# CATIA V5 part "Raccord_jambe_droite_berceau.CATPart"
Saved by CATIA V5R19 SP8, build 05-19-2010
Part number: Raccord_jambe_droite_berceau
Bounding box of the stored display mesh (mm): x 555 to 900, y -1185 to -825, z -35 to 310
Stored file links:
  G:\EU_thinkMotion\CFAO_2010\MMS_groupe2\MMS_groupe2\OK\mmartini\mmartiniCFAO\Raccord_jambe_droite_berceau.CATPart
  C:\Users\Mathieu Martini\Desktop\CFAO\Animation\CFAO.CATProduct
  G:\EU_thinkMotion\CFAO_2010\MMS_groupe2\MMS_groupe2\OK\mmartini\mmartiniCFAO\Squelette.CATPart
  G:\EU_thinkMotion\CFAO_2010\MMS_groupe2\MMS_groupe2\OK\mmartini\mmartiniCFAO\jambe_roue_droite.CATPart
  G:\EU_thinkMotion\CFAO_2010\MMS_groupe2\MMS_groupe2\OK\mmartini\mmartiniCFAO\bielle_droite.CATPart
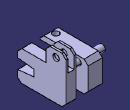
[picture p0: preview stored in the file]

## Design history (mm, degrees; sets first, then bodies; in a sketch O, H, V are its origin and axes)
External parameters (linked from other documents)
  External.diametre_canon = 150 mm
  External.diametre_verin = 120 mm
AxisSystem1: origin (0, 0, 0), X (1, 0, 0), Y (0, 1, 0), Z (0, 0, 1)
Set1
  Sketch1 on Plane1, origin (675, 0, 0), H (0, 1, 0), V (0, 0, 1)
    line L1 (-1185, 190) -> (-825, 190)
    line L2 (-825, 190) -> (-825, -35)
    line L3 (-825, -35) -> (-1185, -35)
    line L4 (-1185, -35) -> (-1185, 190)
    reference projected point E1 (-900, 150) from Line1
    reference projected point E2 (-900, 150) from Line1
    distance E1 L1 = 40 {= External.diametre_verin /3}
    distance L2 E2 = 75 {= External.diametre_canon /2}
    distance L2 L4 = 360 {= External.diametre_verin *3}
    distance L3 L1 = 225 {= External.diametre_canon *1.5}
    horizontal: L1 H, L3 H
    vertical: L2 V, L4 V
Set2
  Plane1 "Plan_verin_droit": linked copy from another document
  Line1 "axe_berceau_jambe": linked copy from another document
  Plane2 "Plan_rayon_ext_verin_droit": linked copy from another document
  Plane3 "Plan_rayon_int_verin_droit": linked copy from another document
  Line2 "Droite_plan_de_construction_verin": linked copy from another document
Body1 (main body)
  Pad1: profile Sketch1, direction (1, 0, 0), up to Plane3, offset -13.6364 {= -External.diametre_canon /11}, opposite side up to Plane2
  Sketch2 on Plane1, origin (675, 0, 0), H (0, 1, 0), V (0, 0, 1)
    circle A1 centre (-900, 150) radius 24
    point P1 (-900, 150)
    reference projected point E1 (-900, 150) from Line1
    radius A1 = 24 {= External.diametre_verin /5}
    coincidence: P1 E1
  Pad2: profile Sketch2, direction (1, 0, 0), length 150 {= External.diametre_canon}, opposite side length 120 {= External.diametre_verin}
  Sketch3 on face of Pad1 from Sketch1.L1, origin (0, 0, 190), H (1, 0, 0), V (0, 1, 0)
    circle A1 centre (675, -1125) radius 24
    point P1 (675, -1125)
    reference projected line E1 through (0, -900) direction (1, 0) from Line1
    reference projected line E2 through (675, 0) direction (0, -1) from Line2
    distance P1 E1 = 225 {= External.diametre_canon *1.5}
    radius A1 = 24 {= External.diametre_verin /5}
    coincidence: P1 E2
  Pocket1: profile Sketch3, direction (0, 0, -1), through (limit type 6)
  Sketch4 on face of Pad1 from Sketch1.L4, origin (0, -1185, 0), H (1, 0, 0), V (0, 0, 1)
    line L1 (628.6364, 152.5) -> (735, 152.5)
    line L2 (735, 152.5) -> (735, 2.5)
    line L3 (735, 2.5) -> (628.6364, 2.5)
    line L4 (628.6364, 2.5) -> (628.6364, 152.5)
    reference projected line E1 (628.6364, -35) -> (628.6364, 190) from edge [face of Pad1 from Sketch1.L4 | end face of Pad1]
    reference projected line E2 (735, 190) -> (735, -35) from edge [face of Pad1 from Sketch1.L4 | start face of Pad1]
    reference projected line E3 (628.6364, -35) -> (735, -35) from edge [face of Pad1 from Sketch1.L3 | face of Pad1 from Sketch1.L4]
    reference projected line E4 (735, 190) -> (628.6364, 190) from edge [face of Pad1 from Sketch1.L1 | face of Pad1 from Sketch1.L4]
    distance L3 E3 = 37.5 {= External.diametre_canon /4}
    distance E4 L1 = 37.5 {= External.diametre_canon /4}
    horizontal: L1 H, L3 H
    vertical: L2 V, L4 V
    coincidence: E1 L4, E2 L2
  Pocket2: profile Sketch4, direction (0, 1, 0), length 125 {= External.diametre_canon /1.2}
  Sketch5 on end face of Pad2, origin (825, 0, 0), H (0, 1, 0), V (0, 0, 1)
    projected line E1 (-1185, 190) -> (-825, 190) from edge [start face of Pad1 | face of Pad1 from Sketch1.L1]
    projected line E2 (-825, -35) -> (-825, 190) from edge [face of Pad1 from Sketch1.L2 | start face of Pad1]
    projected line E3 (-825, -35) -> (-1185, -35) from edge [start face of Pad1 | face of Pad1 from Sketch1.L3]
    line L1 (-1185, 190) -> (-1185, -35)
    vertical: L1 V
  Pad3: profile Sketch5, direction (1, 0, 0), length 75 {= External.diametre_canon /2}
  Sketch6 on end face of Pad3, origin (900, 0, 0), H (0, 1, 0), V (0, 0, 1)
    line L1 (-1185, 115) -> (-1065, 102.5)
    point P1 (-1185, 115)
    point P2 (-1065, 102.5)
    line L2 (-1065, 102.5) -> (-1065, 52.5)
    line L3 (-1065, 52.5) -> (-1185, 40)
    line L4 (-1185, 40) -> (-1185, 115)
    axis line L5 (-1209.8288, 77.5) -> (-1042.0217, 77.5)
    reference projected line E1 (-1185, 190) -> (-1185, -35) from edge [face of Pad3 from Sketch5.L1 | end face of Pad3]
    reference projected line E2 (-1185, -35) -> (-825, -35) from edge [face of Pad3 from Sketch5.E3 | end face of Pad3]
    length L4 = 75 {= External.diametre_canon /2}
    length L2 = 50 {= External.diametre_canon /3}
    distance P2 L5 = 25 {= External.diametre_canon /6}
    distance L5 P1 = 37.5 {= External.diametre_canon /4}
    distance L4 L2 = 120 {= External.diametre_verin}
    distance L5 E2 = 112.5 {= External.diametre_canon *0.75}
    vertical: L2 V, L4 V
    horizontal: L5 H
    coincidence: E1 L4
  Pocket3: profile Sketch6, direction (-1, 0, 0), through (limit type 6)
  Sketch7 on face of Pad3 from Sketch5.E1, origin (0, 0, 190), H (1, 0, 0), V (0, 1, 0)
    line L1 (825, -825) -> (900, -825)
    line L2 (900, -825) -> (900, -975)
    line L3 (900, -975) -> (825, -975)
    line L4 (825, -975) -> (825, -825)
    reference projected line E1 (900, -825) -> (900, -1185) from edge [face of Pad3 from Sketch5.E1 | end face of Pad3]
    reference projected line E2 (825, -825) -> (900, -825) from edge [face of Pad3 from Sketch5.E1 | face of Pad3 from Sketch5.E2]
    reference projected line E3 (825, -825) -> (825, -1185) from edge [start face of Pad3 | face of Pad3 from Sketch5.E1]
    distance L3 L1 = 150 {= External.diametre_canon}
    horizontal: L1 H, L3 H
    vertical: L2 V, L4 V
    coincidence: E1 L2, L1 E2, L4 E3
  Pad4: profile Sketch7, direction (0, 0, 1), length 120 {= External.diametre_verin}
  Sketch8 on end face of Pad4, origin (0, 0, 310), H (1, 0, 0), V (0, 1, 0)
    line L1 (840, -825) -> (885, -825)
    line L2 (885, -825) -> (885, -975)
    line L3 (885, -975) -> (840, -975)
    line L4 (840, -975) -> (840, -825)
    reference projected line E1 (900, -825) -> (825, -825) from edge [face of Pad4 | end face of Pad4]
    reference projected line E2 (825, -975) -> (900, -975) from edge [face of Pad4 from Sketch7.L3 | end face of Pad4]
    reference projected line E3 (900, -975) -> (900, -825) from edge [face of Pad4 | end face of Pad4]
    reference projected line E4 (825, -825) -> (825, -975) from edge [face of Pad4 | end face of Pad4]
    distance L2 E3 = 15 {= External.diametre_canon /10}
    distance L4 E4 = 15 {= External.diametre_canon /10}
    horizontal: L1 H, L3 H
    vertical: L2 V, L4 V
    coincidence: L1 E1, L3 E2
  Pocket4: profile Sketch8, direction (0, 0, -1), up to face of Pad3 from Sketch5.E1
  Sketch9 on face of Pad4, origin (900, 0, 0), H (0, 1, 0), V (0, 0, 1)
    circle A1 centre (-900, 260) radius 24
    point P1 (-900, 260)
    reference projected line E1 (-825, -35) -> (-825, 190) from edge [face of Pad4 | face of Pad4]
    reference projected line E2 (-975, 310) -> (-825, 310) from edge [face of Pad4 | end face of Pad4]
    distance E1 P1 = 75 {= External.diametre_canon /2}
    distance P1 E2 = 50 {= External.diametre_canon /3}
    radius A1 = 24 {= External.diametre_verin /5}
  Pocket5: profile Sketch9, direction (-1, 0, 0), up to face of Pad4
  Chamfer1: length 30 {= External.diametre_canon /5}, angle 45, on edge [face of Pad1 from Sketch1.L1 | face of Pad1 from Sketch1.L2]; edge [face of Pad1 from Sketch1.L1 | face of Pad1 from Sketch1.L4]; edge [face of Pad3 from Sketch5.L1 | face of Pad3]; edge [face of Pad4 | end face of Pad4] (x2); edge [face of Pad4 from Sketch7.L3 | end face of Pad4] (x2)
  Chamfer2: length 24 {= External.diametre_verin /5}, angle 45, on edge [face of Pad3 from Sketch5.E3 | face of Pad3 from Sketch5.L1]; edge [face of Pad1 from Sketch1.L3 | face of Pad1 from Sketch1.L4]
  Chamfer3: length 30 {= External.diametre_canon /5}, angle 45, on edge [face of Pad4 | face of Pad3 from Sketch5.E3]; edge [face of Pad1 from Sketch1.L2 | face of Pad1 from Sketch1.L3]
